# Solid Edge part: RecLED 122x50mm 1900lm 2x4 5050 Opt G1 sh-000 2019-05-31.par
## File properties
Author: sylwester.cabaj
Template: iso metric part.par
Last saved by: sylwester.cabaj
Revision: 1
Application: Solid Edge
Gęstość: 0,000 kg/m^3
Dokładność: 0,990
Username: sylwester.cabaj
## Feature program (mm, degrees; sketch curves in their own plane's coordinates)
body "unnamed Body 1"
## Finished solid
Body 1: solid body, 475 faces, 1203 edges, 733 vertices.
  Faces by surface: plane 221, cylinder 120, spline 80, cone 26, torus 11, sphere 10, spun 7
  Edges by curve: line 652, curve on surface 282, circle 159, ellipse 66, spline 38, intersection 6
Bounding box of the edges (mm; curved faces can reach further): 49.500 x 4.950 x 121.400, from (-24.75, -3.45, -60.7) to (24.75, 1.5, 60.7).
Cylindrical faces by radius (mm): R0.2 x39, R0.2002 x2, R0.2169 x3, R0.25 x12, R0.3 x2, R0.3373 x3, R0.4 x8, R0.4006 x2, R0.4008 x2, R0.525 x2, R0.6 x12, R1 x7, R1.05 x8, R1.0894 x2, R1.1 x14, R1.75 x2
Conical faces (half-angle, radius in mm at the cone's reference point): 0.5 deg R0.5056 x4, 0.5 deg R1.0082 x4, 1 deg R0.5511 x2, 10 deg R0.2132 x2, 10 deg R0.4132 x2, 18.4844 deg R1.0657 x4, 27.363 deg R0.6214 x2, 45 deg R0.575 x2, 45 deg R0.625 x4
Toroidal faces (ring radius, tube radius in mm): R0.1 r0.2 x1, R0.8 r0.2 x4, R0.8522 r0.3 x2, R0.9002 r0.2 x1, R0.9018 r0.2 x1, R1.3 r0.2 x2
Spherical faces by radius (mm): R0.2 x8, R0.6 x2
Planar faces by outward normal: +x 21, +y 8, +z 17, -x 21, -y 36, -z 26, oblique 92
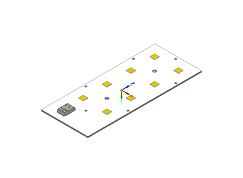
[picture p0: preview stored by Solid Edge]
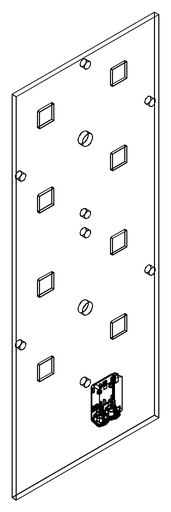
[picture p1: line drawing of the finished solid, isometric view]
